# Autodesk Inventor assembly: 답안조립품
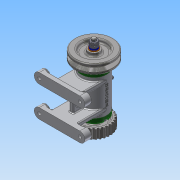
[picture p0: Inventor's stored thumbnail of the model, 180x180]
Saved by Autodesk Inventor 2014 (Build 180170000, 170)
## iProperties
Created: 2015-11
Part Number: 답안조립품
Document SubType Name: Assembly
Designer: 103-17
Author: 103-17
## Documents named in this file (16)
- C:\Users\103-17\Desktop\451110V1018\답안조립품.iam
- C:\Users\103-17\Desktop\451110V1018\1-본체.ipt
- C:\Users\103-17\Desktop\451110V1018\베어링 15 x 32 x 9.ipt
- C:\Users\103-17\Desktop\451110V1018\축.ipt
- C:\Users\103-17\Desktop\451110V1018\키 3 x 3 x 12.ipt
- C:\Users\103-17\Desktop\451110V1018\커버.ipt
- C:\Users\103-17\Desktop\451110V1018\오일 실 15 25 7.ipt
- C:\Users\103-17\Desktop\451110V1018\볼트 M4 x 12.ipt
- C:\Users\103-17\Desktop\451110V1018\스퍼기어.ipt
- C:\Users\103-17\Desktop\451110V1018\와셔 8x17.ipt
- C:\Users\103-17\Desktop\451110V1018\스프링와셔 8.ipt
- C:\Users\103-17\Desktop\451110V1018\너트 M 8.ipt
- C:\Users\103-17\Desktop\451110V1018\V벨트풀리.ipt
- C:\Users\103-17\Desktop\451110V1018\니플 M 6 x 0.75.ipt
- C:\Users\103-17\Desktop\451110V1018\와셔 6x11.5.ipt
- C:\Users\103-17\Desktop\451110V1018\볼트 M 6 x 8.ipt
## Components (12 placed, 4 different names)
1. 1-본체:1
2. KS B 2023 6002 - 15 x 32 x 9:1
3. KS B 2023 6002 - 15 x 32 x 9:2
4. V벨트풀리:1 — 플러쉬:2, 각도:6
5. ISO 4762 M4 x 12:1
6. ISO 4762 M4 x 12:3
7. ISO 4762 M4 x 12:4
8. ISO 4762 M4 x 12:5
9. ISO 4762 M4 x 12:2
10. ISO 4762 M4 x 12:6
11. ISO 4762 M4 x 12:7
12. ISO 4762 M4 x 12:8
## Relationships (2: Flush 1, Angle 1)
- 플러쉬:2 [Flush]: V벨트풀리:1
- 각도:6 [Angle]: V벨트풀리:1
